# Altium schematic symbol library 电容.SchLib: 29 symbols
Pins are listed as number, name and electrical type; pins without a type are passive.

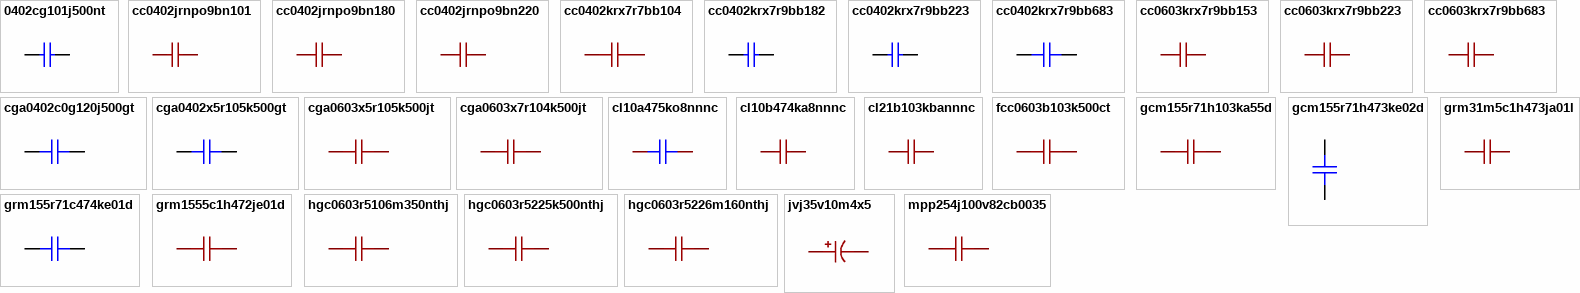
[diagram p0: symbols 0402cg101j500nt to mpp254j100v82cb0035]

## 0402cg101j500nt
designator C??  (value not drawn)
容值:100pF;精度:±5%;额定电压:50V;温度系数:C0G;; Manufacturer: FH(风华); AddInBom: yes; ModelId: 36a51122f27c49738f86b3bfa98863e0; ModelName: C0402_L1.0-W0.5-H0.5; ModelTransform: 39.37,19.685,0,0,0,0,0,0,0; Value: 100pF; Tolerance: ±5%; Voltage Rating: 50V; Temperature Coefficient: C0G
footprint C0402
pins: 1, 2

## cc0402jrnpo9bn101
designator C??  (value not drawn)
容值:100pF;精度:±5%;额定电压:50V;温度系数:NP0;; Manufacturer: YAGEO(国巨); AddInBom: yes; ModelId: 36a51122f27c49738f86b3bfa98863e0; ModelName: C0402_L1.0-W0.5-H0.5; ModelTransform: 39.37,19.685,0,0,0,0,0,0,0; Value: 100pF; Tolerance: ±5%; Voltage Rating: 50V; Temperature Coefficient: NP0
footprint C0402
pins: 1, 2

## cc0402jrnpo9bn180
designator C??  (value not drawn)
容值:18pF;精度:±5%;额定电压:50V;温度系数:NP0;; Manufacturer: YAGEO(国巨); AddInBom: yes; ModelId: 36a51122f27c49738f86b3bfa98863e0; ModelName: C0402_L1.0-W0.5-H0.5; ModelTransform: 39.37,19.685,0,0,0,0,0,0,0; Value: 18pF; Tolerance: ±5%; Voltage Rating: 50V; Temperature Coefficient: NP0
footprint C0402
pins: 1, 2

## cc0402jrnpo9bn220
designator C??  (value not drawn)
容值:22pF;精度:±5%;额定电压:50V;温度系数:NP0;; Manufacturer: YAGEO(国巨); AddInBom: yes; ModelId: 36a51122f27c49738f86b3bfa98863e0; ModelName: C0402_L1.0-W0.5-H0.5; ModelTransform: 39.37,19.685,0,0,0,0,0,0,0; Value: 22pF; Tolerance: ±5%; Voltage Rating: 50V; Temperature Coefficient: NP0
footprint C0402
pins: 1, 2

## cc0402krx7r7bb104
designator C??  (value not drawn)
容值:100nF;精度:±10%;额定电压:16V;温度系数:X7R;; Manufacturer: YAGEO(国巨); AddInBom: yes; ModelId: 36a51122f27c49738f86b3bfa98863e0; ModelName: C0402_L1.0-W0.5-H0.5; ModelTransform: 39.37,19.685,0,0,0,0,0,0,0; Value: 100nF; Tolerance: ±10%; Voltage Rating: 16V; Temperature Coefficient: X7R
footprint C0402
pins: 1, 2

## cc0402krx7r9bb182
designator C??  (value not drawn)
容值:1.8nF;精度:±10%;额定电压:50V;材质(温度系数):X7R;; Manufacturer: YAGEO(国巨); AddInBom: yes; ModelId: 36a51122f27c49738f86b3bfa98863e0; ModelName: C0402_L1.0-W0.5-H0.5; ModelTransform: 39.37,19.685,0,0,0,0,0,0,0; Value: 1.8nF; Tolerance: ±10%; Voltage Rated: 50V; Temperature Coefficient: X7R
footprint C0402
pins: 1, 2

## cc0402krx7r9bb223
designator C??  (value not drawn)
容值:22nF;精度:±10%;额定电压:50V;温度系数:X7R;; Manufacturer: YAGEO(国巨); AddInBom: yes; ModelId: 36a51122f27c49738f86b3bfa98863e0; ModelName: C0402_L1.0-W0.5-H0.5; ModelTransform: 39.37,19.685,0,0,0,0,0,0,0; Value: 22nF; Tolerance: ±10%; Voltage Rating: 50V; Temperature Coefficient: X7R
footprint C0402
pins: 1, 2

## cc0402krx7r9bb683
designator C??  (value not drawn)
容值:68nF;精度:±10%;额定电压:50V;温度系数:X7R;; Manufacturer: YAGEO(国巨); AddInBom: yes; ModelId: 36a51122f27c49738f86b3bfa98863e0; ModelName: C0402_L1.0-W0.5-H0.5; ModelTransform: 39.37,19.685,0,0,0,0,0,0,0; Value: 68nF; Tolerance: ±10%; Voltage Rating: 50V; Temperature Coefficient: X7R
footprint C0402
pins: 1, 2

## cc0603krx7r9bb153
designator C??  (value not drawn)
容值:15nF;精度:±10%;额定电压:50V;材质(温度系数):X7R;; Manufacturer: YAGEO(国巨); AddInBom: yes; ModelId: ac125912035d415993ca9572d50418b1; ModelName: C0603_L1.6-W0.8-H0.8; ModelTransform: 62.992,31.496,0,0,0,0,0,0,0; Value: 15nF; Tolerance: ±10%; Voltage Rated: 50V; Temperature Coefficient: X7R
footprint C0603
pins: 1, 2

## cc0603krx7r9bb223
designator C??  (value not drawn)
容值:22nF;精度:±10%;额定电压:50V;温度系数:X7R;; Manufacturer: YAGEO(国巨); AddInBom: yes; ModelId: ac125912035d415993ca9572d50418b1; ModelName: C0603_L1.6-W0.8-H0.8; ModelTransform: 62.992,31.496,0,0,0,0,0,0,0; Value: 22nF; Tolerance: ±10%; Voltage Rating: 50V; Temperature Coefficient: X7R
footprint C0603
pins: 1, 2

## cc0603krx7r9bb683
designator C??  (value not drawn)
容值:68nF;精度:±10%;额定电压:50V;温度系数:X7R;; Manufacturer: YAGEO(国巨); AddInBom: yes; ModelId: ac125912035d415993ca9572d50418b1; ModelName: C0603_L1.6-W0.8-H0.8; ModelTransform: 62.992,31.496,0,0,0,0,0,0,0; Value: 68nF; Tolerance: ±10%; Voltage Rating: 50V; Temperature Coefficient: X7R
footprint C0603
pins: 1, 2

## cga0402c0g120j500gt
designator C??  (value not drawn)
容值:12pF;精度:±5%;额定电压:50V;温度系数:C0G;; Manufacturer: HRE(芯声); AddInBom: yes; ModelId: 36a51122f27c49738f86b3bfa98863e0; ModelName: C0402_L1.0-W0.5-H0.5; ModelTransform: 39.37,19.685,0,0,0,0,0,0,0; Value: 12pF; Tolerance: ±5%; Voltage Rating: 50V; Temperature Coefficient: C0G
footprint C0402
pins: 1, 2

## cga0402x5r105k500gt
designator C??  (value not drawn)
容值:1uF;精度:±10%;额定电压:50V;温度系数:X5R;; Manufacturer: HRE(芯声); AddInBom: yes; ModelId: 36a51122f27c49738f86b3bfa98863e0; ModelName: C0402_L1.0-W0.5-H0.5; ModelTransform: 39.37,19.685,0,0,0,0,0,0,0; Value: 1uF; Tolerance: ±10%; Voltage Rating: 50V; Temperature Coefficient: X5R
footprint C0402
pins: 1, 2

## cga0603x5r105k500jt
designator C??  (value not drawn)
容值:1uF;精度:±10%;额定电压:50V;温度系数:X5R;; Manufacturer: HRE(芯声); AddInBom: yes; ModelId: ac125912035d415993ca9572d50418b1; ModelName: C0603_L1.6-W0.8-H0.8; ModelTransform: 62.992,31.496,0,0,0,0,0,0,0; Value: 1uF; Tolerance: ±10%; Voltage Rating: 50V; Temperature Coefficient: X5R
footprint C0603
pins: 1, 2

## cga0603x7r104k500jt
designator C??  (value not drawn)
容值:100nF;精度:±10%;额定电压:50V;温度系数:X7R;; Manufacturer: HRE(芯声); AddInBom: yes; ModelId: ac125912035d415993ca9572d50418b1; ModelName: C0603_L1.6-W0.8-H0.8; ModelTransform: 62.992,31.496,0,0,0,0,0,0,0; Value: 100nF; Tolerance: ±10%; Voltage Rating: 50V; Temperature Coefficient: X7R
footprint C0603
pins: 1, 2

## cl10a475ko8nnnc
designator C??  (value not drawn)
容值:4.7uF;精度:±10%;额定电压:16V;温度系数:X5R;; Manufacturer: SAMSUNG(三星); AddInBom: yes; ModelId: ac125912035d415993ca9572d50418b1; ModelName: C0603_L1.6-W0.8-H0.8; ModelTransform: 62.992,31.496,0,0,0,0,0,0,0; Value: 4.7uF; Tolerance: ±10%; Voltage Rating: 16V; Temperature Coefficient: X5R
footprint C0603
pins: 1, 2

## cl10b474ka8nnnc
designator C??  (value not drawn)
容值:470nF;精度:±10%;额定电压:25V;温度系数:X7R;; Manufacturer: SAMSUNG(三星); AddInBom: yes; ModelId: ac125912035d415993ca9572d50418b1; ModelName: C0603_L1.6-W0.8-H0.8; ModelTransform: 62.992,31.496,0,0,0,0,0,0,0; Value: 470nF; Tolerance: ±10%; Voltage Rating: 25V; Temperature Coefficient: X7R
footprint C0603
pins: 1, 2

## cl21b103kbannnc
designator C??  (value not drawn)
容值:10nF;精度:±10%;额定电压:50V;温度系数:X7R;; Manufacturer: SAMSUNG(三星); AddInBom: yes; ModelId: 1ba041120af144c991958decab20d241; ModelName: C0805_L2.0-W1.3-H1.3; ModelTransform: 78.74,51.181,0,0,0,0,0,0.0005,0; Value: 10nF; Tolerance: ±10%; Voltage Rating: 50V; Temperature Coefficient: X7R
footprint C0805
pins: 1, 2

## fcc0603b103k500ct
designator C??  (value not drawn)
容值:10nF;精度:±10%;额定电压:50V;温度系数:X7R;; Manufacturer: FOJAN(富捷); AddInBom: yes; ModelId: ac125912035d415993ca9572d50418b1; ModelName: C0603_L1.6-W0.8-H0.8; ModelTransform: 62.992,31.496,0,0,0,0,0,0,0; Value: 10nF; Tolerance: ±10%; Voltage Rating: 50V; Temperature Coefficient: X7R
footprint C0603
pins: 1, 2

## gcm155r71h103ka55d
designator C??  (value not drawn)
容值:10nF;精度:±10%;额定电压:50V;温度系数:X7R;; Manufacturer: muRata(村田); AddInBom: yes; ModelId: 36a51122f27c49738f86b3bfa98863e0; ModelName: C0402_L1.0-W0.5-H0.5; ModelTransform: 39.37,19.685,0,0,0,0,0,0,0; Value: 10nF; Tolerance: ±10%; Voltage Rating: 50V; Temperature Coefficient: X7R
footprint C0402
pins: 1, 2

## gcm155r71h473ke02d
designator C??  (value not drawn)
容值:47nF;精度:±10%;额定电压:50V;温度系数:X7R;; Manufacturer: muRata(村田); AddInBom: yes; ModelId: 36a51122f27c49738f86b3bfa98863e0; ModelName: C0402_L1.0-W0.5-H0.5; ModelTransform: 39.37,19.685,0,0,0,0,0,0,0; Value: 47nF; Tolerance: ±10%; Voltage Rating: 50V; Temperature Coefficient: X7R
footprint C0402
pins: 1, 2

## grm31m5c1h473ja01l
designator C??  (value not drawn)
容值:47nF;精度:±5%;额定电压:50V;温度系数:C0G;; Manufacturer: muRata(村田); AddInBom: yes; ModelId: e4be705b945545a48e666415e3682bd8; ModelName: C1206_L3.2-W1.6-H1.3; ModelTransform: 125.984,62.992,0,0,0,0,0,0,0; Value: 47nF; Tolerance: ±5%; Voltage Rating: 50V; Temperature Coefficient: C0G
footprint C1206
pins: 1, 2

## grm155r71c474ke01d
designator C??  (value not drawn)
容值:470nF;精度:±10%;额定电压:16V;温度系数:X7R;; Manufacturer: muRata(村田); AddInBom: yes; ModelId: 36a51122f27c49738f86b3bfa98863e0; ModelName: C0402_L1.0-W0.5-H0.5; ModelTransform: 39.37,19.685,0,0,0,0,0,0,0; Value: 470nF; Tolerance: ±10%; Voltage Rating: 16V; Temperature Coefficient: X7R
footprint C0402
pins: 1, 2

## grm1555c1h472je01d
designator C??  (value not drawn)
容值:4.7nF;精度:±5%;额定电压:50V;温度系数:C0G;; Manufacturer: muRata(村田); AddInBom: yes; ModelId: 36a51122f27c49738f86b3bfa98863e0; ModelName: C0402_L1.0-W0.5-H0.5; ModelTransform: 39.37,19.685,0,0,0,0,0,0,0; Value: 4.7nF; Tolerance: ±5%; Voltage Rating: 50V; Temperature Coefficient: C0G
footprint C0402
pins: 1, 2

## hgc0603r5106m350nthj
designator C??  (value not drawn)
容值:10uF;精度:±20%;额定电压:35V;温度系数:X5R;; Manufacturer: Chinocera(华瓷); AddInBom: yes; ModelId: ac125912035d415993ca9572d50418b1; ModelName: C0603_L1.6-W0.8-H0.8; ModelTransform: 62.992,31.496,0,0,0,0,0,0,0; Value: 10uF; Tolerance: ±20%; Voltage Rating: 35V; Temperature Coefficient: X5R
footprint C0603
pins: 1, 2

## hgc0603r5225k500nthj
designator C??  (value not drawn)
容值:2.2uF;精度:±10%;额定电压:50V;温度系数:X5R;; Manufacturer: Chinocera(华瓷); AddInBom: yes; ModelId: ac125912035d415993ca9572d50418b1; ModelName: C0603_L1.6-W0.8-H0.8; ModelTransform: 62.992,31.496,0,0,0,0,0,0,0; Value: 2.2uF; Tolerance: ±10%; Voltage Rating: 50V; Temperature Coefficient: X5R
footprint C0603
pins: 1, 2

## hgc0603r5226m160nthj
designator C??  (value not drawn)
容值:22uF;精度:±20%;额定电压:16V;温度系数:X5R;; Manufacturer: Chinocera(华瓷); AddInBom: yes; ModelId: ac125912035d415993ca9572d50418b1; ModelName: C0603_L1.6-W0.8-H0.8; ModelTransform: 62.992,31.496,0,0,0,0,0,0,0; Value: 22uF; Tolerance: ±20%; Voltage Rating: 16V; Temperature Coefficient: X5R
footprint C0603
pins: 1, 2

## jvj35v10m4x5
designator C??  (value not drawn)
容值:10uF;精度:±20%;额定电压:35V;纹波电流:14mA@120Hz;; Manufacturer: JIERR(捷而瑞); AddInBom: yes; ModelId: d5abac2407cc4bb7a22453350802a0e2; ModelName: CAP-SMD_L4.3-W4.3-H5.3-LS5.1; ModelTransform: 169.291,181.102,0,90,0,0,0.376,-0.001,0; Value: 10uF; Tolerance: ±20%; Voltage Rating: 35V; Lifetime: 2000hrs@105℃
footprint CAP-SMD_BD4.0-L4.3-W4.3-FD
pins: 1, 2

## mpp254j100v82cb0035
designator C??  (value not drawn)
容值:250nF;精度:±5%;额定电压:100V;工作温度:-40℃~+105℃;; Manufacturer: KNSCHA(科尼盛); AddInBom: yes; ModelId: aaf58ab59f614e21806e16d8f477b590; ModelName: CAP-TH_L9.0-W3.5-P7.50-D0.6; ModelTransform: 354.23268,137.04036,0,0,0,0,0,0,-137.795; Value: 250nF; Tolerance: ±5%; Voltage Rating: 100V
footprint CAP-TH_L9.0-W3.5-P7.50-D0.6
pins: 1, 2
